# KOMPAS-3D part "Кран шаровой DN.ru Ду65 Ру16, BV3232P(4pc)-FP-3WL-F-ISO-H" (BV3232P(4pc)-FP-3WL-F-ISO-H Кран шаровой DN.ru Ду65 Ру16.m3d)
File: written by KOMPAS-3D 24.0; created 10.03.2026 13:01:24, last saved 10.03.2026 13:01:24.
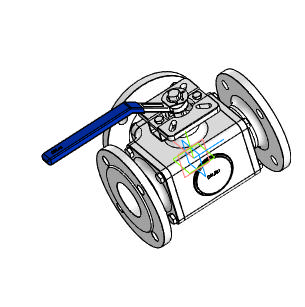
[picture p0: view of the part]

Document properties: Автор: R2D2; Полное имя файла: BV3232P(4pc)-FP-3WL-F-ISO-H Кран шаровой DN.ru Ду65 Ру16.cdw

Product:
- Part/product: Кран шаровой DN.ru Ду65 Ру16  | designation BV3232P(4pc)-FP-3WL-F-ISO-H
    Масса: 26.5
    Раздел спецификации: Прочие изделия
    Форматы листов документа: A2
    Примечание: D160-36361

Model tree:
1. Операция без истории:1

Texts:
  BV3232P(4pc)-FP-3WL-F-ISO-H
